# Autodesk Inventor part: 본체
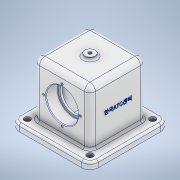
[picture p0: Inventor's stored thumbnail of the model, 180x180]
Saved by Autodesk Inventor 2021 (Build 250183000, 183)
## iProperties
Created: 2022-07
Part Number: 본체
Material: 알루미늄 6061
Document SubType Name: Modeling
Designer: i
Density: 2.7 g/cm^3
Appearance: 알루미늄 - 평지
Mass: 1059.83 g
Surface Area: 721.846 cm^2
Volume: 392.53 cm^3
Author: i
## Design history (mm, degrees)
sketch "스케치1"
  geometry: L1 (-58, 58)-(58, 58); L2 (58, 58)-(58, -58); L3 (58, -58)-(-58, -58); L4 (-58, -58)-(-58, 58); L5 (-58, 58)-(58, -58); L6 (58, 58)-(-58, -58); 1 further point
  constraints: 12 end point, 2 midpoint, 2 parallel, 1 horizontal, 1 perpendicular
  dimensions: "d0" = 116 distance of L1.end L2.end; "d1" = 116 distance of L2.end L3.end
extrude "돌출1" new body sketch "스케치1" distance "d2" = 10; taper "d3" = 0 deg
sketch "스케치2"
  geometry: L1 (-41, -41)-(41, -41); L2 (41, -41)-(41, 41); L3 (41, 41)-(-41, 41); L4 (-41, 41)-(-41, -41); L5 (-41, -41)-(41, 41); L6 (41, -41)-(-41, 41); 1 further point
  constraints: 12 end point, 2 midpoint, 2 parallel, 1 horizontal, 1 perpendicular
  dimensions: "d4" = 82 distance of L3.end L1.start; "d5" = 82 distance of L2.end L3.end
extrude "돌출2" join sketch "스케치2" distance "d6" = 80; taper "d7" = 0 deg
sketch "스케치3"
  geometry: C1 r 7.5 at (0, 0); 1 further point
  constraints: 1 centre point, 1 coincident
  dimensions: "d8" = 15 diameter of C1
extrude "돌출3" join sketch "스케치3" distance "d9" = 4; taper "d10" = 0 deg
sketch "스케치4"
  geometry: L1 (-30, 21)-(30, 21); L2 (30, 21)-(30, -21); L3 (30, -21)-(-30, -21); L4 (-30, -21)-(-30, 21); L5 (-30, 21)-(30, -21); L6 (30, 21)-(-30, -21); C1 r 7.5 at (0, 0) reference; 1 further point
  constraints: 12 end point, 2 midpoint, 2 parallel, 1 horizontal, 1 perpendicular
  dimensions: "d11" = 42 distance of L1.end L2.end; "d12" = 60 distance of L2.end L3.end
extrude "돌출4" cut sketch "스케치4" distance "d13" = 80; taper "d14" = 0 deg
sketch "스케치5"
  geometry: L1 (41, -10)-(41, 38); L2 (82, 0)-(82, 80) reference; L3 (0, 0)-(0, 80) reference
  constraints: 2 end point, 1 vertical
  dimensions: "d15" = 48 distance of L1.start L1.end; "d16" = 41 distance between parallel lines of L2 L1 (derived); "d17" = 41 distance between parallel lines of L1 L3 (derived)
hole "구멍1" sketch "스케치5" at (41, 38) diameter "d18" = 47; stored, may be unused: countersink angle "d22" = 90 deg, drill point angle "d24" = 0 deg; dims "d19" = 8, "d20" = 4, "d21" = 2, "d23" = 17
sketch "스케치6"
  geometry: C1 r 23.5 at (0, 0) reference; 2 further points
  constraints: 1 coincident
hole "구멍2" sketch "스케치6" at (0, 0) diameter "d25" = 40; stored, may be unused: countersink angle "d29" = 90 deg, drill point angle "d31" = 0 deg; dims "d26" = 8, "d27" = 4, "d28" = 2, "d30" = 17
sketch "스케치7"
  geometry: C1 r 7.5 at (0, 0) reference; 2 further points
  constraints: 1 coincident
hole "구멍3" sketch "스케치7" at (0, 0) diameter "d32" = 4.917; stored, may be unused: countersink angle "d36" = 90 deg, drill point angle "d38" = 0 deg; dims "d33" = 80, "d34" = 4, "d35" = 2, "d37" = 17
sketch "스케치8"
  geometry: L1 (41, 38)-(41, 65); C1 r 23.5 at (41, 38) reference; 1 further point
  constraints: 2 end point, 1 vertical
  dimensions: "d39" = 27 distance of L1.start L1.end
hole "구멍4" sketch "스케치8" at (41, 65) diameter "d40" = 3.242; stored, may be unused: countersink angle "d44" = 90 deg, drill point angle "d46" = 118 deg; dims "d41" = 8, "d42" = 4, "d43" = 2, "d45" = 10
fillet "모깎기1" dims "d50" = 12
sketch "스케치9"
  geometry: A1 r 12 centre (46, -46) between (46, -58) and (58, -46) reference; A2 r 12 centre (46, 46) between (58, 46) and (46, 58) reference; A3 r 12 centre (-46, -46) between (-58, -46) and (-46, -58) reference; A4 r 12 centre (-46, 46) between (-46, 58) and (-58, 46) reference; 5 further points
  constraints: 4 coincident
hole "구멍5" sketch "스케치9" at (46, -46), (46, 46), (-46, -46), (-46, 46) diameter "d51" = 9; stored, may be unused: countersink angle "d55" = 90 deg, drill point angle "d57" = 118 deg; dims "d52" = 8, "d53" = 4, "d54" = 2, "d56" = 10
sketch "스케치10"
  geometry: L1 (48.5, 84)-(33.5, 84) reference; L2 (-5, -10)-(87, -10) reference; L3 (0, 0)-(0, 80) reference; L4 (82, 0)-(82, 80) reference; 2 further points
  constraints: 1 other
  dimensions: "d58" = 48 distance from line of L2 point (41, 38); "d59" = 41 distance from line of L3 point (41, 38) (= d60); "d60" = 41 distance from line of L4 point (41, 38) (derived)
feature "엠보싱1" sketch "스케치10" dims "d0" = 116, "d1" = 116, "d61" = 0.5, "d62" = 0
fillet "모깎기2" dims "d63" = 8
fillet "모깎기3" dims "d64" = 8
chamfer "모따기1" distance "d65" = 1; stored, may be unused: second distance "d66" = 2, angle "d67" = 45 deg
fillet "모깎기4" dims "d68" = 0.6
fillet "모깎기5" dims "d69" = 3
fillet "모깎기6" dims "d70" = 3
fillet "모깎기7" dims "d71" = 3
fillet "모깎기8" dims "d72" = 3
node "솔리드1"
mirror "미러1"
pattern_circular "원형 패턴1" dims angle "d48" = 360 deg
mirror "미러2"
feature "A9D066F2-1C7D-4E18-AEED-F7BC21143FA4" dims "d18" = 47, "d19" = 8, "d20" = 4, "d21" = 2, "d22" = 90 deg, "d23" = 17, "d24" = 0
